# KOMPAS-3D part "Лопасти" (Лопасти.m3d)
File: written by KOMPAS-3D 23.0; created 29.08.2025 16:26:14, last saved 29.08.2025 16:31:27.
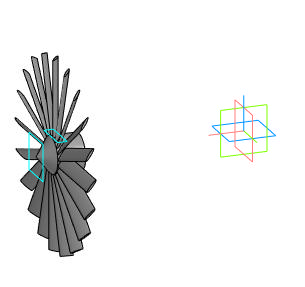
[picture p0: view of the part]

Document properties: Автор: Inspektor_Kot; Полное имя файла: I:\Autodesk Inventor Projects\ИМ-ИТ ЦД\Вариант 4\Лопасти.m3d

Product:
- Part/product: Лопасти

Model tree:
1. Эскиз:1  (with: Элемент выдавливания:3)
2. Элемент выдавливания:1
     Расстояние 2 = 10
3. Эскиз:2  (with: Элемент выдавливания:1)
4. Смещенная плоскость:1  (with: Элемент выдавливания:1)
     Расстояние = 16
5. Эскиз:3
6. Элемент по сечениям:1
7. Касательная плоскость:1  (with: Элемент выдавливания:1)
8. Эскиз:4  (with: Элемент по сечениям:1, Элемент выдавливания:1)
9. Элемент выдавливания:2
     Расстояние 1 = 83
10. Массив по концентрической сетке:1  (with: Элемент выдавливания:2, Касательная плоскость:1, Элемент выдавливания:1)  (20 pattern instances)
     Шаг 2 = 360
11. Элемент выдавливания:3  (with: Элемент выдавливания:1)
     Расстояние 1 = 20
